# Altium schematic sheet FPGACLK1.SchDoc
size B; PageSetup: Record=PageOptions|CenterHorizontal=True|CenterVertical=True|PrintScale=1.08|XCorrection=1.00|YCorrection=1.00|PrintKind=0|BorderSize=5000000|LeftOffset=0|BottomOffset=0|Orientation=2|PaperLength=1000|PaperWidth=1000|Scale=100|PaperSource=7|PrintQuality=-4|MediaType=1|DitherType=10|PaperKind=11x17|PrintScaleMode=1
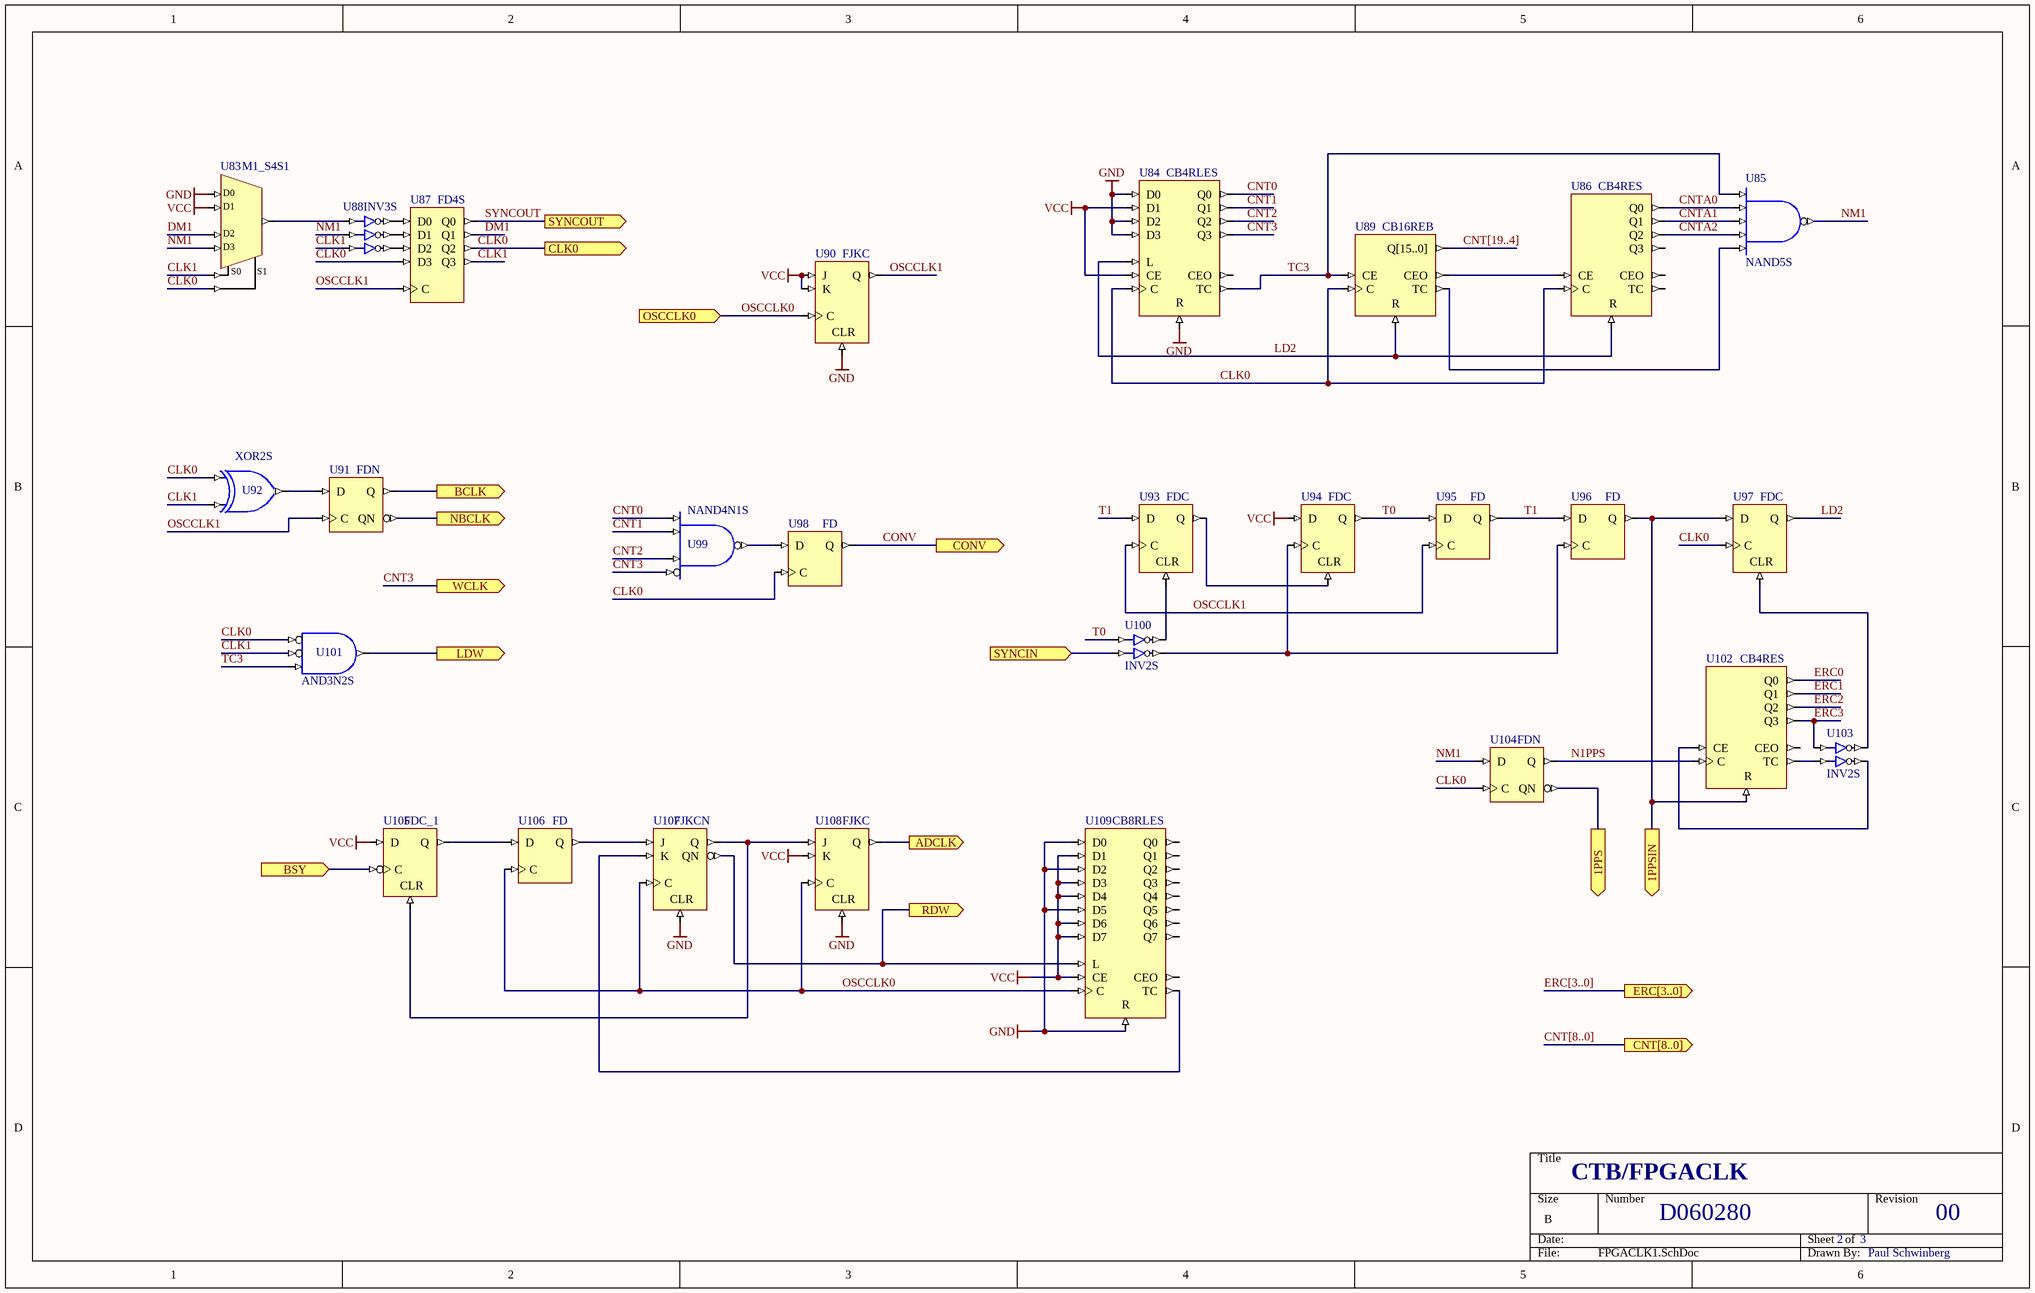
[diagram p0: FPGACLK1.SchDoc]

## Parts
U83  M1_S4S1
U84  CB4RLES
U85  NAND5S
U86  CB4RES
U87  FD4S
U88  INV3S
U89  CB16REB
U90  FJKC
U91  FDN
U92  XOR2S
U93  FDC
U94  FDC
U95  FD
U96  FD
U97  FDC
U98  FD
U99  NAND4N1S
U100  INV2S
U101  AND3N2S
U102  CB4RES
U103  INV2S
U104  FDN
U105  FDC_1
U106  FD
U107  FJKCN
U108  FJKC
U109  CB8RLES

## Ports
1PPS (out), 1PPSIN (out), ADCLK (out), BCLK (out), BSY (in), CLK0 (out), CNT[8..0] (out), CONV (out), ERC[3..0] (out), LDW (out), NBCLK (out), OSCCLK0 (in), RDW (out), SYNCIN (in), SYNCOUT (out), WCLK (out)

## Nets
GND: U83.D0 U84.D0 U84.D2 U84.D3 U84.R U90.CLR U107.CLR U108.CLR U109.D0 U109.D2 U109.D5 U109.R
VCC: U83.D1 U84.CE U84.D1 U90.J U90.K U94.D U105.D U108.K U109.CE U109.D1 U109.D3 U109.D4 U109.D6 U109.D7
1PPS: U104.QN ; port 1PPS
1PPSIN: U96.Q U97.D U102.R ; port 1PPSIN
ADCLK: U108.Q ; port ADCLK
BCLK: U91.Q ; port BCLK
BSY: U105.C ; port BSY
CLK0: U83.S1 U84.C U86.C U87.D3 U87.Q2 U89.C U92.I0 U97.C U98.C U101.I0 U104.C ; port CLK0
CLK1: U83.S0 U87.Q3 U88.I2 U92.I1 U101.I1
CNT0: U84.Q0 U99.I3
CNT1: U84.Q1 U99.I2
CNT2: U84.Q2 U99.I1
CNT3: U84.Q3 U99.I0 ; port WCLK
CNTA0: U85.I1 U86.Q0
CNTA1: U85.I2 U86.Q1
CNTA2: U85.I3 U86.Q2
CONV: U98.Q ; port CONV
DM1: U83.D2 U87.Q1
ERC0: U102.Q0
ERC1: U102.Q1
ERC2: U102.Q2
ERC3: U102.Q3 U103.I0
LD2: U84.L U86.R U89.R U97.Q
LDW: U101.O ; port LDW
N1PPS: U102.C U104.Q
NBCLK: U91.QN ; port NBCLK
NM1: U83.D3 U85.O U88.I1 U104.D
OSCCLK0: U90.C U106.C U107.C U108.C U109.C ; port OSCCLK0
OSCCLK1: U87.C U90.Q U91.C U93.C U95.C
RDW: U107.QN U109.L ; port RDW
SYNCIN: U100.I1 ; port SYNCIN
SYNCOUT: U87.Q0 ; port SYNCOUT
T0: U94.Q U95.D U100.I0
T1: U93.D U95.Q U96.D
TC3: U84.TC U85.I0 U89.CE U101.I2
NetU83_O: U83.O U88.I0
NetU85_I4: U85.I4 U89.TC
NetU86_CE: U86.CE U89.CEO
NetU87_D0: U87.D0 U88.O0
NetU87_D1: U87.D1 U88.O1
NetU87_D2: U87.D2 U88.O2
NetU91_D: U91.D U92.O
NetU93_CLR: U93.CLR U100.O0
NetU93_Q: U93.Q U94.CLR
NetU94_C: U94.C U96.C U100.O1
NetU97_CLR: U97.CLR U103.O0
NetU98_D: U98.D U99.O
NetU102_CE: U102.CE U103.O1
NetU102_TC: U102.TC U103.I1
NetU105_CLR: U105.CLR U107.Q U108.J
NetU105_Q: U105.Q U106.D
NetU106_Q: U106.Q U107.J
NetU107_K: U107.K U109.TC

Not connected (* = marked no-connect by the designer): U84 CEO; U86 CEO Q3 TC; U89 Q[15..0]; U102 CEO; U109 CEO Q0 Q1 Q2 Q3 Q4 Q5 Q6 Q7

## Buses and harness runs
bus CNT[8..0] = port CNT[8..0]
bus CNT[19..4]
bus ERC[3..0] = port ERC[3..0]

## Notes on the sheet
- CTB/FPGACLK
- D060280
- 2
- 3
- 00
- Paul Schwinberg

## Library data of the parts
U83 = M1_S4S1: 4x1-Single Wire to 1x1-Single Wire Multiplexer; SubClass: SnS1; PortSize: 1; PortStyle: Single Pin Version; ArchiveName: GENERIC; VHDLIB_SIM: GENERIC_LIB
U84 = CB4RLES: 4-Bit Loadable Cascadable Binary Counter with Clock Enable and Synchronous Reset, Single Pin Version; XilinxEquivalent: CB4RLE; ClockTrigger: Rising; Enable: High; Loadable: True; PortSize: 4; ArchiveName: GENERIC; VHDLIB_SIM: GENERIC_LIB
U85 = NAND5S: 5-Input NAND Gate, Single Pin Version; XilinxEquivalent: NAND5; FunctionalClass: Logic Primitive; PortSize: 5; ArchiveName: GENERIC; VHDLIB_SIM: GENERIC_LIB
U86 U102 = CB4RES: 4-Bit Cascadable Binary Counter with Clock Enable and Synchronous Reset, Single Pin Version; XilinxEquivalent: CB4RE; ClockTrigger: Rising; Enable: High; PortSize: 4; ArchiveName: GENERIC; VHDLIB_SIM: GENERIC_LIB
U87 = FD4S: 4-Bit D-Type Flip-Flop, Single Pin Version; XilinxEquivalent: FD4; SubClass: FD; ClockTrigger: Rising; PortSize: 4; ArchiveName: GENERIC; VHDLIB_SIM: GENERIC_LIB
U88 = INV3S: 3-Bit Inverter, Single Pin Version; FunctionalClass: Logic Primitive; SubClass: INV; PortSize: 3; ArchiveName: GENERIC; VHDLIB_SIM: GENERIC_LIB
U89 = CB16REB: 16-Bit Cascadable Binary Counter with Clock Enable and Synchronous Reset, Bus Version; XilinxEquivalent: CB16RE; ClockTrigger: Rising; Enable: High; PortSize: 16; ArchiveName: GENERIC; VHDLIB_SIM: GENERIC_LIB
U90 U108 = FJKC: J-K Flip-Flop with Asynchronous Clear; SubClass: JK; ClockTrigger: Rising; ArchiveName: GENERIC; VHDLIB_SIM: GENERIC_LIB
U91 U104 = FDN: D-Type Flip-Flop with Inverted and Non-Inverted Outputs; SubClass: FD; ClockTrigger: Rising; ArchiveName: GENERIC; VHDLIB_SIM: GENERIC_LIB
U92 = XOR2S: 2-Input Exclusive-OR Gate, Single Pin Version; XilinxEquivalent: XOR2; FunctionalClass: Logic Primitive; SubClass: XOR; PortSize: 2; ArchiveName: GENERIC; VHDLIB_SIM: GENERIC_LIB
U93 U94 U97 = FDC: D-Type Flip-Flop with Asynchronous Clear; SubClass: FD; ClockTrigger: Rising; ArchiveName: GENERIC; VHDLIB_SIM: GENERIC_LIB
U95 U96 U98 U106 = FD: D-Type Flip-Flop; ClockTrigger: Rising; ArchiveName: GENERIC; VHDLIB_SIM: GENERIC_LIB
U99 = NAND4N1S: 4-Input NAND Gate with Active Low A Input, Single Pin Version; XilinxEquivalent: NAND4B1; FunctionalClass: Logic Primitive; PortSize: 4; ArchiveName: GENERIC; VHDLIB_SIM: GENERIC_LIB
U100 U103 = INV2S: 2-Bit Inverter, Single Pin Version; XilinxEquivalent: INV2; FunctionalClass: Logic Primitive; SubClass: INV; PortSize: 2; ArchiveName: GENERIC; VHDLIB_SIM: GENERIC_LIB
U101 = AND3N2S: 3-Input AND Gate with Active Low A and B Inputs, Single Pin Version; XilinxEquivalent: AND3B2; FunctionalClass: Logic Primitive; PortSize: 3; ArchiveName: GENERIC; VHDLIB_SIM: GENERIC_LIB
U105 = FDC_1: D-Type Negative Edge Flip-Flop with Asynchronous Clear; SubClass: FD; ClockTrigger: Falling; ArchiveName: GENERIC; VHDLIB_SIM: GENERIC_LIB
U107 = FJKCN: J-K Flip-Flop with Asynchronous Clear and Inverted and Non-Inverted Outputs; SubClass: JK; ClockTrigger: Rising; ArchiveName: GENERIC; VHDLIB_SIM: GENERIC_LIB
U109 = CB8RLES: 8-Bit Loadable Cascadable Binary Counter with Clock Enable and Synchronous Reset, Single Pin Version; ClockTrigger: Rising; Enable: High; Loadable: True; PortSize: 8; ArchiveName: GENERIC; VHDLIB_SIM: GENERIC_LIB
